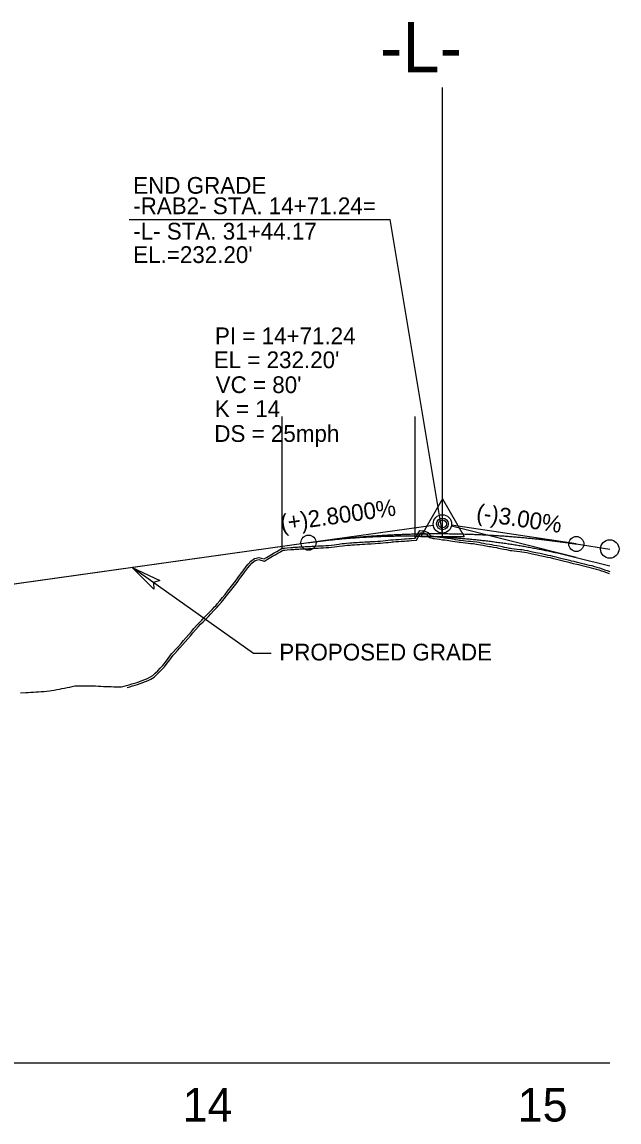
# Model space of a CAD drawing. Extents: x 2115752 to 2121174, y 562881 to 567245.
# Drawn here: x 2120468 to 2120646.3, y 564096.3 to 564424.9 of the extents above; entities that cross this region are included whole.
import ezdxf

# ---------------------------------------------------------------- set-up
doc = ezdxf.new("R2010")
doc.units = 0
for name, color, linetype in [('Exist Profile Cell', 7, 'Continuous'), ('Exist Vertical Profile Ground Line', 7, 'Continuous'), ('Exist Vertical Profile Horizontal Axis Label Major', 7, 'Continuous'), ('Prop PFL VPI Symbol CELL', 7, 'Continuous'), ('Prop Terminator CELL', 7, 'Continuous'), ('Prop Vertical Profile Curve Label', 7, 'Continuous'), ('Prop Vertical Profile Grade', 7, 'Continuous'), ('Prop Vertical Profile Grade Label', 7, 'Continuous'), ('Prop VPI Label', 7, 'Continuous'), ('Scratch_Level_1', 7, 'Continuous'), ('Scratch_Level_2', 7, 'Continuous'), ('Scratch_Level_4', 7, 'Continuous')]:
    doc.layers.add(name, color=color, linetype=linetype)

msp = doc.modelspace()

# ---------------------------------------------------------------- linework, layer by layer
at = {"layer": 'Exist Profile Cell'}
msp.add_line((2120072.308606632, 564113.9363014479), (2120643.547504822, 564113.9363014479), dxfattribs=at)
at = {"layer": 'Exist Vertical Profile Ground Line'}
for points in [[(2120571.126303, 564269.5851899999), (2120571.899448, 564269.6305999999), (2120572.2054890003, 564269.648115), (2120573.445737, 564269.7239750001), (2120574.218882, 564269.763525), (2120574.9920260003, 564269.8076749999), (2120575.7651710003, 564269.88683), (2120576.5383160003, 564269.9660749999), (2120577.31146, 564270.0514499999), (2120578.084605, 564270.1379900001), (2120578.457485, 564270.1790949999), (2120578.85775, 564270.2053599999), (2120579.630894, 564270.2570949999), (2120580.404039, 564270.3125199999), (2120581.177184, 564270.3667499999), (2120582.214405, 564270.44201), (2120582.723473, 564270.4835999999), (2120583.4966180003, 564270.54586), (2120584.269762, 564270.60676), (2120585.4389770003, 564270.6706999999), (2120585.816052, 564271.2865749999), (2120586.844244, 564272.98385), (2120587.3623410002, 564272.87723), (2120588.135486, 564272.8462149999), (2120589.170336, 564272.37474), (2120589.9353610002, 564271.429675), (2120590.5709530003, 564271.28874), (2120590.888884, 564271.231645), (2120591.228064, 564271.1832549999), (2120592.001209, 564271.07225), (2120592.774354, 564270.9605449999), (2120593.699647, 564270.8315549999), (2120594.3167290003, 564270.7533799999), (2120595.0859600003, 564270.65527), (2120596.03364, 564270.5334399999), (2120596.624421, 564270.4417300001), (2120597.393652, 564270.3211249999), (2120598.162883, 564270.1832349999), (2120598.622059, 564270.100565), (2120598.932114, 564270.064805), (2120599.701344, 564269.975655), (2120600.470575, 564269.886095), (2120601.320942, 564269.7780399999), (2120602.009037, 564269.73417), (2120602.7782670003, 564269.6840149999), (2120603.8463270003, 564269.5390699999), (2120604.419691, 564269.44352), (2120605.0859600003, 564269.3143849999), (2120605.8551910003, 564269.164575), (2120606.624421, 564269.0198550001), (2120607.597155, 564268.84941), (2120608.162883, 564268.756495), (2120608.932114, 564268.6296649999), (2120609.8525090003, 564268.479665), (2120610.470575, 564268.3464899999), (2120611.3921350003, 564268.1477099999), (2120612.009037, 564268.031385), (2120612.7782670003, 564267.886245), (2120613.5474980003, 564267.738165), (2120613.9154330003, 564267.657655), (2120614.3167290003, 564267.6096699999), (2120615.0859600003, 564267.5173849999), (2120615.8551910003, 564267.42481), (2120616.7272840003, 564267.3150749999), (2120617.393652, 564267.2451549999), (2120618.162883, 564267.1044899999), (2120618.932114, 564266.962385), (2120619.701344, 564266.803185), (2120620.470575, 564266.643785), (2120621.438602, 564266.44366), (2120622.009037, 564266.3182499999), (2120622.7782670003, 564266.14906), (2120624.3167290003, 564265.810405), (2120625.0859600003, 564265.6378149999), (2120625.8551910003, 564265.4652949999), (2120626.895638, 564265.2305000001), (2120627.393652, 564265.11402), (2120628.162883, 564264.9342799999), (2120628.9650310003, 564264.7470549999), (2120629.701344, 564264.5462649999), (2120630.711188, 564264.2713299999), (2120631.496054, 564264.07893), (2120632.009037, 564263.9544449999), (2120632.7782670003, 564263.768265), (2120633.8082500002, 564263.5214249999), (2120634.3167290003, 564263.3907999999), (2120635.0859600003, 564263.1935599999), (2120635.85519, 564262.9966999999), (2120636.624421, 564262.8111399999), (2120637.393652, 564262.643905), (2120638.162883, 564262.465855), (2120638.932114, 564262.2589899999), (2120639.701344, 564262.05302), (2120640.470575, 564261.8329749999), (2120641.239806, 564261.548785), (2120642.009037, 564261.265205), (2120642.7782670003, 564260.9822549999), (2120643.5486000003, 564260.6995706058)], [(2120499.223849, 564226.679885), (2120499.996993, 564226.90431), (2120500.770138, 564227.1347599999), (2120501.543283, 564227.3712099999), (2120502.3164270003, 564227.61364), (2120503.0895720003, 564227.862025), (2120503.8627170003, 564228.1260899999), (2120504.635861, 564228.4507299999), (2120505.409006, 564228.779965), (2120506.182151, 564229.14486), (2120507.054514, 564229.6430599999), (2120507.72844, 564230.30551), (2120508.501585, 564231.073885), (2120509.274729, 564231.850565), (2120510.047874, 564232.6625699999), (2120510.821019, 564233.68147), (2120511.594164, 564234.70818), (2120512.6634150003, 564236.1416849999), (2120513.140453, 564236.65721), (2120513.913598, 564237.5029999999), (2120514.6867420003, 564238.3589649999), (2120515.4598870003, 564239.2250199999), (2120516.2330320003, 564240.1010749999), (2120517.006176, 564240.987025), (2120517.779321, 564241.88279), (2120518.552466, 564242.788265), (2120519.32561, 564243.7033549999), (2120520.098755, 564244.6267899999), (2120520.8719, 564245.3904550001), (2120521.645044, 564246.1638699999), (2120522.4181890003, 564246.9469499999), (2120523.1913340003, 564247.739615), (2120523.964478, 564248.54178), (2120524.737623, 564249.3533549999), (2120525.510768, 564250.17426), (2120525.814845, 564250.50076), (2120526.2839120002, 564251.063065), (2120527.057057, 564251.997125), (2120527.830202, 564252.93832), (2120528.603346, 564253.88654), (2120529.376491, 564254.8417000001), (2120530.149636, 564255.8036849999), (2120530.563672, 564256.32245), (2120530.92278, 564256.7981599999), (2120531.695925, 564257.8287399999), (2120532.46907, 564258.86561), (2120533.2422140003, 564259.908665), (2120534.0153590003, 564260.9577899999), (2120534.906826, 564262.1752399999), (2120535.561648, 564262.9160999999), (2120536.334793, 564263.794425), (2120537.3777960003, 564264.5803949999), (2120537.881082, 564264.71278), (2120538.738401, 564264.9371349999), (2120539.427372, 564264.7528299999), (2120540.302041, 564264.5166499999), (2120540.973661, 564264.9260849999), (2120541.988218, 564265.5027849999), (2120542.51995, 564265.810615), (2120543.293095, 564266.258405), (2120544.06624, 564266.7063549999), (2120544.8393840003, 564267.15441), (2120545.713458, 564267.66102), (2120546.3856740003, 564267.7022899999), (2120547.158818, 564267.7791899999), (2120548.2203800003, 564267.880855), (2120548.8157740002, 564267.9286849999), (2120549.163767, 564267.947935), (2120549.478252, 564267.969845), (2120550.251397, 564268.022245), (2120550.635874, 564268.0475649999), (2120551.024542, 564268.07225), (2120551.389818, 564268.0947749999), (2120551.797686, 564268.1114549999), (2120552.570831, 564268.1424049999), (2120553.640323, 564268.1858399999), (2120554.11712, 564268.22141), (2120554.582763, 564268.2553999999), (2120554.890265, 564268.27374), (2120555.66341, 564268.318685), (2120556.4365540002, 564268.3627149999), (2120557.21083, 564268.408325), (2120557.982844, 564268.436275), (2120558.755988, 564268.48168), (2120559.529133, 564268.52573), (2120560.302278, 564268.5871199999), (2120561.17734, 564268.7209999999), (2120561.8928380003, 564268.8079049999), (2120562.621712, 564268.905045), (2120563.6238800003, 564269.0372499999), (2120564.2900260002, 564269.103455), (2120564.9411460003, 564269.166915), (2120565.9179350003, 564269.256845), (2120566.487435, 564269.3018149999), (2120566.942115, 564269.3370599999), (2120567.26058, 564269.35755), (2120568.033724, 564269.406065), (2120568.806869, 564269.45176), (2120569.580014, 564269.4899099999), (2120570.353158, 564269.5386249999), (2120571.126303, 564269.5851899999)], [(2120467.524917, 564224.513685), (2120469.071207, 564224.58402), (2120469.844351, 564224.6207499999), (2120470.617496, 564224.6605199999), (2120471.390641, 564224.703335), (2120472.1637850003, 564224.749185), (2120472.9369300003, 564224.79806), (2120473.7100750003, 564224.849965), (2120474.483219, 564224.9048899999), (2120475.256364, 564224.96283), (2120476.178979, 564225.03614), (2120476.802653, 564225.153185), (2120477.575798, 564225.30089), (2120478.348943, 564225.451185), (2120479.122087, 564225.6040549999), (2120479.5667620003, 564225.6934499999), (2120479.895232, 564225.7554599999), (2120480.668377, 564225.903925), (2120481.441521, 564226.0548899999), (2120482.214666, 564226.2083299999), (2120482.987811, 564226.36423), (2120483.7609550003, 564226.5225800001), (2120484.160701, 564226.6057099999), (2120484.5341000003, 564226.5957399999), (2120485.3072450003, 564226.5786349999), (2120486.080389, 564226.565055), (2120486.853534, 564226.5550099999), (2120487.626679, 564226.548495), (2120488.399823, 564226.5455149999), (2120489.172968, 564226.5460699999), (2120489.946113, 564226.545585), (2120490.719257, 564226.5007649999), (2120491.492402, 564226.459385), (2120492.2655470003, 564226.421455), (2120493.038691, 564226.38697), (2120493.811836, 564226.355945), (2120494.584981, 564226.32838), (2120495.3581250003, 564226.3042749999), (2120496.1312700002, 564226.28363), (2120496.904415, 564226.2664549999), (2120497.689826, 564226.25258), (2120498.450704, 564226.46151), (2120499.223849, 564226.679885)]]:
    msp.add_lwpolyline(points, dxfattribs=at)
at = {"layer": 'Prop PFL VPI Symbol CELL'}
for p, q in [((2120593.541600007, 564282.4183000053), (2120587.091600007, 564271.2183000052)), ((2120593.541600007, 564282.4183000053), (2120600.041600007, 564271.2183000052)), ((2120587.091600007, 564271.2183000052), (2120600.041600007, 564271.2183000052))]:
    msp.add_line(p, q, dxfattribs=at)
for radius in [1.75, 1.2000000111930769]:
    msp.add_circle((2120593.5486000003, 564274.9363), radius, dxfattribs=at)
at = {"layer": 'Prop Terminator CELL'}
msp.add_lwpolyline([(2120507.293844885, 564255.4878591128), (2120500.8488790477, 564261.9581694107), (2120509.156707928, 564258.0284774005), (2120507.2931225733, 564257.3885167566)], close=True, dxfattribs=at)
at = {"layer": 'Prop Vertical Profile Curve Label'}
msp.add_circle((2120553.5486000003, 564269.3362267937), 2.25, dxfattribs=at)
at = {"layer": 'Prop Vertical Profile Grade'}
msp.add_line((2120442.3086, 564253.7624232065), (2120553.5486000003, 564269.3362267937), dxfattribs=at)
msp.add_spline([(2120553.5486000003, 564269.3362267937), (2120555.1486000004, 564269.5555896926), (2120556.7486000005, 564269.765672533), (2120558.3486, 564269.9664753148), (2120559.9486000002, 564270.157998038), (2120561.5486000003, 564270.3402407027), (2120563.1486000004, 564270.5132033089), (2120564.7486000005, 564270.6768858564), (2120566.3486, 564270.8312883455), (2120567.9486000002, 564270.9764107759), (2120569.5486000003, 564271.1122531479), (2120571.1486000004, 564271.2388154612), (2120572.7486000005, 564271.3560977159), (2120574.3486, 564271.4640999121), (2120575.9486000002, 564271.5628220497), (2120577.5486000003, 564271.6522641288), (2120579.1486000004, 564271.7324261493), (2120580.7486000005, 564271.8033081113), (2120582.3486, 564271.8649100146), (2120583.9486000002, 564271.9172318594), (2120585.5486000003, 564271.9602736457), (2120587.1486000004, 564271.9940353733), (2120588.7486000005, 564272.0185170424), (2120590.3486, 564272.033718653), (2120591.9486000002, 564272.039640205), (2120593.5486000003, 564272.0362816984), (2120593.548606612, 564272.0362816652)], degree=3, dxfattribs=at)
at = {"layer": 'Prop VPI Label'}
for p, q in [((2120499.9531031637, 564365.8427743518), (2120577.930122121, 564365.8427743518)), ((2120593.5486000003, 564272.0362816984), (2120577.930122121, 564365.8427743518)), ((2120553.5486000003, 564269.3362267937), (2120590.8251608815, 564274.5550135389)), ((2120633.5486000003, 564268.9363), (2120596.2681749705, 564274.5283637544)), ((2120633.5486000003, 564268.9363), (2120643.5486000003, 564267.4363))]:
    msp.add_line(p, q, dxfattribs=at)
msp.add_lwpolyline([(2120542.409575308, 564236.2452354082), (2120537.1099301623, 564236.2452354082), (2120500.8488790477, 564261.9581694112)], dxfattribs=at)
for centre, radius in [((2120593.5486000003, 564274.9363), 2.75), ((2120633.5486000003, 564268.9363), 2.25)]:
    msp.add_circle(centre, radius, dxfattribs=at)
at = {"layer": 'Scratch_Level_1'}
for p, q in [((2120593.548606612, 564270.850757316), (2120593.548606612, 564405.3290151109)), ((2120545.7086066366, 564267.6607714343), (2120545.7086066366, 564307.0630293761)), ((2120585.4386066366, 564270.6707290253), (2120585.4386066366, 564307.0630293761))]:
    msp.add_line(p, q, dxfattribs=at)
for points in [[(2120571.1629486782, 564268.9612652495), (2120571.935626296, 564269.0066477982), (2120572.242423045, 564269.0242060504), (2120573.480781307, 564269.0999504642), (2120574.2526633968, 564269.1394358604), (2120575.0416948, 564269.1844931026), (2120575.8288619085, 564269.2650836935), (2120576.6044799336, 564269.3445821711), (2120577.3805213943, 564269.4302771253), (2120578.1536083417, 564269.5168106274), (2120578.5122152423, 564269.5563422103), (2120578.899076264, 564269.5817276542), (2120579.6741036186, 564269.6335886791), (2120580.4482497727, 564269.6890854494), (2120581.22166506, 564269.743334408), (2120582.2624672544, 564269.818854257), (2120582.7740028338, 564269.8606458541), (2120583.546241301, 564269.9228328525), (2120584.3113713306, 564269.9831015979), (2120585.8006949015, 564270.0645471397), (2120586.349850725, 564270.9614810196), (2120587.1502765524, 564272.2827738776), (2120587.286322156, 564272.254776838), (2120587.9879312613, 564272.226631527), (2120588.777205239, 564271.8670403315), (2120589.586931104, 564270.8667546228), (2120590.4480164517, 564270.675819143), (2120590.7894790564, 564270.6144982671), (2120591.13951522, 564270.564559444), (2120591.912110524, 564270.4536333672), (2120592.686520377, 564270.3417456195), (2120593.617221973, 564270.212001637), (2120594.2379169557, 564270.1333689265), (2120595.006577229, 564270.0353317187), (2120595.9458422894, 564269.91458351), (2120596.5280796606, 564269.8241997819), (2120597.290096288, 564269.7047258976), (2120598.0523718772, 564269.5680827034), (2120598.5307907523, 564269.4819482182), (2120598.8603329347, 564269.4439406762), (2120599.6292279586, 564269.3548294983), (2120600.3950410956, 564269.265667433), (2120601.2616081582, 564269.1555539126), (2120601.9688213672, 564269.1104650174), (2120602.7158349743, 564269.061758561), (2120603.752912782, 564268.921018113), (2120604.3088411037, 564268.8283737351), (2120604.9667604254, 564268.7008570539), (2120605.7376729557, 564268.5507195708), (2120606.512702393, 564268.404908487), (2120607.492570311, 564268.2332134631), (2120608.061398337, 564268.1397893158), (2120608.8310095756, 564268.0128966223), (2120609.736344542, 564267.865351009), (2120610.338860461, 564267.7355265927), (2120611.268317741, 564267.5350431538), (2120611.893190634, 564267.4172151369), (2120612.66125289, 564267.2722954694), (2120613.421605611, 564267.125924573), (2120613.8112888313, 564267.0406557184), (2120614.2424022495, 564266.9891052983), (2120615.011396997, 564266.8968486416), (2120615.778837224, 564266.8044891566), (2120616.65565165, 564266.6941600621), (2120617.3046988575, 564266.6260574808), (2120618.0499003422, 564266.4897866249), (2120618.811997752, 564266.3489994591), (2120619.574601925, 564266.1911707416), (2120620.3438990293, 564266.0317570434), (2120621.3082294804, 564265.8323962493), (2120621.8748074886, 564265.707834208), (2120622.6439571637, 564265.5386618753), (2120624.1811337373, 564265.2002898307), (2120624.9491587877, 564265.027970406), (2120625.718012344, 564264.8555350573), (2120626.755675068, 564264.6213683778), (2120627.2513783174, 564264.5054288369), (2120628.0207491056, 564264.3256561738), (2120628.8117333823, 564264.1410368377), (2120629.5370368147, 564263.9432491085), (2120630.554668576, 564263.6661938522), (2120631.347956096, 564263.4717294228), (2120631.861828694, 564263.347028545), (2120632.631923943, 564263.1606391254), (2120633.6576557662, 564262.9148179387), (2120634.161356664, 564262.7854204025), (2120634.930864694, 564262.5881093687), (2120635.704423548, 564262.3901415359), (2120636.4847330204, 564262.2019090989), (2120637.256787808, 564262.0340601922), (2120638.0112107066, 564261.8594377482), (2120638.7701304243, 564261.6553457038), (2120639.5345579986, 564261.4506616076), (2120640.276055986, 564261.238549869), (2120641.0234152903, 564260.9624402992), (2120641.793062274, 564260.6787069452), (2120642.5627288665, 564260.3955963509), (2120643.3332871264, 564260.1128292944)], [(2120499.3980794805, 564226.079661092), (2120500.173375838, 564226.3047108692), (2120500.9507985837, 564226.5364359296), (2120501.728178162, 564226.7741809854), (2120502.505513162, 564227.0179251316), (2120503.28617684, 564227.2687256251), (2120504.0849660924, 564227.5415493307), (2120504.87928285, 564227.8750796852), (2120505.664915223, 564228.2096322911), (2120506.470943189, 564228.5900467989), (2120507.4348439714, 564229.1405233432), (2120508.167794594, 564229.8609928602), (2120508.9433486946, 564230.6317620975), (2120509.722578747, 564231.4145559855), (2120510.5246256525, 564232.2569155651), (2120511.319601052, 564233.3045850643), (2120512.09429502, 564234.3333520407), (2120513.144618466, 564235.7414815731), (2120513.6004781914, 564236.2341196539), (2120514.3761614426, 564237.0826864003), (2120515.151772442, 564237.9413826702), (2120515.927315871, 564238.8101243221), (2120516.7027909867, 564239.6888195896), (2120517.478199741, 564240.5773647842), (2120518.253546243, 564241.4756804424), (2120519.0288302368, 564242.3836605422), (2120519.8039272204, 564243.3010620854), (2120520.5589929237, 564244.2029033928), (2120521.3125176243, 564244.94718867), (2120522.088434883, 564245.7233779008), (2120522.8642783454, 564246.5091910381), (2120523.640049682, 564247.3045486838), (2120524.415748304, 564248.1093641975), (2120525.191379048, 564248.9235484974), (2120525.9669448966, 564249.747023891), (2120526.2838470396, 564250.0872947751), (2120526.764614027, 564250.6636254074), (2120527.539264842, 564251.5995046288), (2120528.313873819, 564252.5424818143), (2120529.0884423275, 564253.4924488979), (2120529.8629729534, 564254.4493207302), (2120530.637464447, 564255.4129811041), (2120531.057420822, 564255.9391640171), (2120531.4221702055, 564256.4223471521), (2120532.1964233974, 564257.4544043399), (2120532.9706456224, 564258.4927190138), (2120533.7448356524, 564259.5371852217), (2120534.5190608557, 564260.587776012), (2120535.394132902, 564261.7828359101), (2120536.0303657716, 564262.5026643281), (2120536.761824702, 564263.3336322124), (2120537.6557200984, 564264.0072400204), (2120538.0396933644, 564264.1082408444), (2120538.736644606, 564264.2906286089), (2120539.2651508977, 564264.1492491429), (2120540.398213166, 564263.8432972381), (2120541.2908270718, 564264.3874552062), (2120542.299218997, 564264.960650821), (2120542.8331391, 564265.2697475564), (2120543.6063787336, 564265.7175923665), (2120544.3795932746, 564266.1655826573), (2120545.152779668, 564266.6136622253), (2120545.899126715, 564267.0462421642), (2120546.4357713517, 564267.0791889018), (2120547.219539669, 564267.157145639), (2120548.275198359, 564267.2582452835), (2120548.858064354, 564267.3050688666), (2120549.2027482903, 564267.3241358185), (2120549.5211023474, 564267.3463153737), (2120550.29306371, 564267.3986351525), (2120550.676217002, 564267.4238679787), (2120551.063583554, 564267.4484703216), (2120551.4218246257, 564267.4705615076), (2120551.8229549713, 564267.4869659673), (2120552.5960117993, 564267.5179124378), (2120553.67626285, 564267.5617843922), (2120554.1631192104, 564267.5981048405), (2120554.6241205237, 564267.6317560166), (2120554.9270058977, 564267.6498206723), (2120555.6993137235, 564267.6947170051), (2120556.472698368, 564267.7387607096), (2120557.240516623, 564267.7839903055), (2120558.012474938, 564267.8119382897), (2120558.7920847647, 564267.857723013), (2120559.5716497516, 564267.9021387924), (2120560.374369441, 564267.96587711), (2120561.262300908, 564268.1017260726), (2120561.9718033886, 564268.1879028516), (2120562.703865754, 564268.2854677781), (2120563.6956746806, 564268.4163062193), (2120564.351245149, 564268.481460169), (2120565.0001096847, 564268.544700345), (2120565.9711866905, 564268.6341044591), (2120566.536186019, 564268.678719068), (2120566.986332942, 564268.7136126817), (2120567.3002157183, 564268.733807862), (2120568.071732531, 564268.7822207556), (2120568.8407084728, 564268.8276693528), (2120569.6150681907, 564268.8658792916), (2120570.391596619, 564268.914807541), (2120571.1638774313, 564268.9613204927)]]:
    msp.add_lwpolyline(points, dxfattribs=at)
at = {"layer": 'Scratch_Level_2'}
for p, q in [((2120593.541600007, 564282.4183000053), (2120587.091600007, 564271.2183000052)), ((2120593.541600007, 564282.4183000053), (2120600.041600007, 564271.2183000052)), ((2120553.5486000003, 564269.3362267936), (2120590.8251608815, 564274.5550135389)), ((2120633.5486000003, 564264.9363), (2120596.2164918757, 564274.2693270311)), ((2120437.3086, 564253.0624140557), (2120553.5486000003, 564269.3362267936)), ((2120587.091600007, 564271.2183000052), (2120600.041600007, 564271.2183000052)), ((2120633.5486000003, 564264.9363), (2120643.5486000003, 564262.4363))]:
    msp.add_line(p, q, dxfattribs=at)
for radius in [1.75, 1.2000000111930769]:
    msp.add_circle((2120593.5486000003, 564274.9363), radius, dxfattribs=at)
msp.add_spline([(2120553.5486000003, 564269.3362267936), (2120555.1486000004, 564269.5539896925), (2120556.7486000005, 564269.759272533), (2120558.3486, 564269.9520753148), (2120559.9486000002, 564270.132398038), (2120561.5486000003, 564270.3002407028), (2120563.1486000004, 564270.455603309), (2120564.7486000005, 564270.5984858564), (2120566.3486, 564270.7288883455), (2120567.9486000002, 564270.8468107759), (2120569.5486000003, 564270.9522531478), (2120571.1486000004, 564271.0452154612), (2120572.7486000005, 564271.1256977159), (2120574.3486, 564271.193699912), (2120575.9486000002, 564271.2492220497), (2120577.5486000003, 564271.2922641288), (2120579.1486000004, 564271.3228261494), (2120580.7486000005, 564271.3409081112), (2120582.3486, 564271.3465100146), (2120583.9486000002, 564271.3396318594), (2120585.5486000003, 564271.3202736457), (2120587.1486000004, 564271.2884353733), (2120588.7486000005, 564271.2441170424), (2120590.3486, 564271.187318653), (2120591.9486000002, 564271.118040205), (2120593.5486000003, 564271.0362816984), (2120595.1486000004, 564270.9420431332), (2120596.7486000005, 564270.8353245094), (2120598.3486, 564270.7161258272), (2120599.9486000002, 564270.5844470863), (2120601.5486000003, 564270.4402882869), (2120603.1486000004, 564270.283649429), (2120604.7486000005, 564270.1145305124), (2120606.3486, 564269.9329315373), (2120607.9486000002, 564269.7388525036), (2120609.5486000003, 564269.5322934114), (2120611.1486000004, 564269.3132542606), (2120612.7486000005, 564269.0817350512), (2120614.3486, 564268.8377357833), (2120615.9486000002, 564268.5812564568), (2120617.5486000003, 564268.3122970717), (2120619.1486000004, 564268.0308576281), (2120620.7486000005, 564267.736938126), (2120622.3486, 564267.4305385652), (2120623.9486000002, 564267.1116589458), (2120625.5486000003, 564266.7802992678), (2120627.1486000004, 564266.4364595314), (2120628.7486000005, 564266.0801397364), (2120630.3486, 564265.7113398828), (2120631.9486000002, 564265.3300599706), (2120633.5486000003, 564264.9363)], degree=3, dxfattribs=at)
at = {"layer": 'Scratch_Level_4'}
msp.add_circle((2120643.5486000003, 564267.4363), 2.75, dxfattribs=at)
msp.add_spline([(2120593.548606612, 564272.0362816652), (2120595.1486000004, 564272.0236431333), (2120596.7486000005, 564272.0017245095), (2120598.3486, 564271.9705258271), (2120599.9486000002, 564271.9300470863), (2120601.5486000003, 564271.880288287), (2120603.1486000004, 564271.8212494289), (2120604.7486000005, 564271.7529305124), (2120606.3486, 564271.6753315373), (2120607.9486000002, 564271.5884525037), (2120609.5486000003, 564271.4922934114), (2120611.1486000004, 564271.3868542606), (2120612.7486000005, 564271.2721350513), (2120614.3486, 564271.1481357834), (2120615.9486000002, 564271.0148564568), (2120617.5486000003, 564270.8722970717), (2120619.1486000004, 564270.720457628), (2120620.7486000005, 564270.5593381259), (2120622.3486, 564270.3889385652), (2120623.9486000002, 564270.2092589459), (2120625.5486000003, 564270.020299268), (2120627.1486000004, 564269.8220595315), (2120628.7486000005, 564269.6145397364), (2120630.3486, 564269.3977398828), (2120631.9486000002, 564269.1716599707), (2120633.5486000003, 564268.9363)], degree=3, dxfattribs=at)

# ---------------------------------------------------------------- texts
at = {"layer": 'Exist Vertical Profile Horizontal Axis Label Major'}
for s, p in [('14', (2120515.9570848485, 564096.4363)), ('15', (2120616.0495090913, 564096.4363))]:
    msp.add_text(s, height=10, dxfattribs=at).set_placement(p)
at = {"layer": 'Prop Vertical Profile Curve Label'}
for s, p in [("VC = 80'", (2120525.820262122, 564314.0159031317)), ('K = 14', (2120525.5581408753, 564306.8605074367)), ('DS = 25mph', (2120525.404890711, 564299.4339448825))]:
    msp.add_text(s, height=5, dxfattribs=at).set_placement(p)
at = {"layer": 'Prop Vertical Profile Grade Label'}
for s, rotation, p in [('(+)2.8000%', 7.969713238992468, (2120545.475092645, 564272.6517089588)), ('(-)3.00%', 351.46923439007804, (2120603.447967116, 564276.0246388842))]:
    msp.add_text(s, height=5, rotation=rotation, dxfattribs=at).set_placement(p)
at = {"layer": 'Prop VPI Label'}
for s, p in [('END GRADE', (2120501.182896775, 564373.5479735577)), ('-RAB2- STA. 14+71.24=', (2120501.182896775, 564367.4500480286)), ('-L- STA. 31+44.17', (2120501.182896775, 564359.8639090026)), ("EL.=232.20'", (2120501.182896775, 564352.8658321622)), ('PI = 14+71.24', (2120525.6011287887, 564328.6071454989)), ("EL = 232.20'", (2120525.2359065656, 564321.4577069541)), ('PROPOSED GRADE', (2120544.829867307, 564234.148355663))]:
    msp.add_text(s, height=5, dxfattribs=at).set_placement(p)
at = {"layer": 'Scratch_Level_1'}
msp.add_text('-L-', height=15, dxfattribs=at).set_placement((2120574.898624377, 564409.8500684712))

doc.saveas('drawing.dxf')
